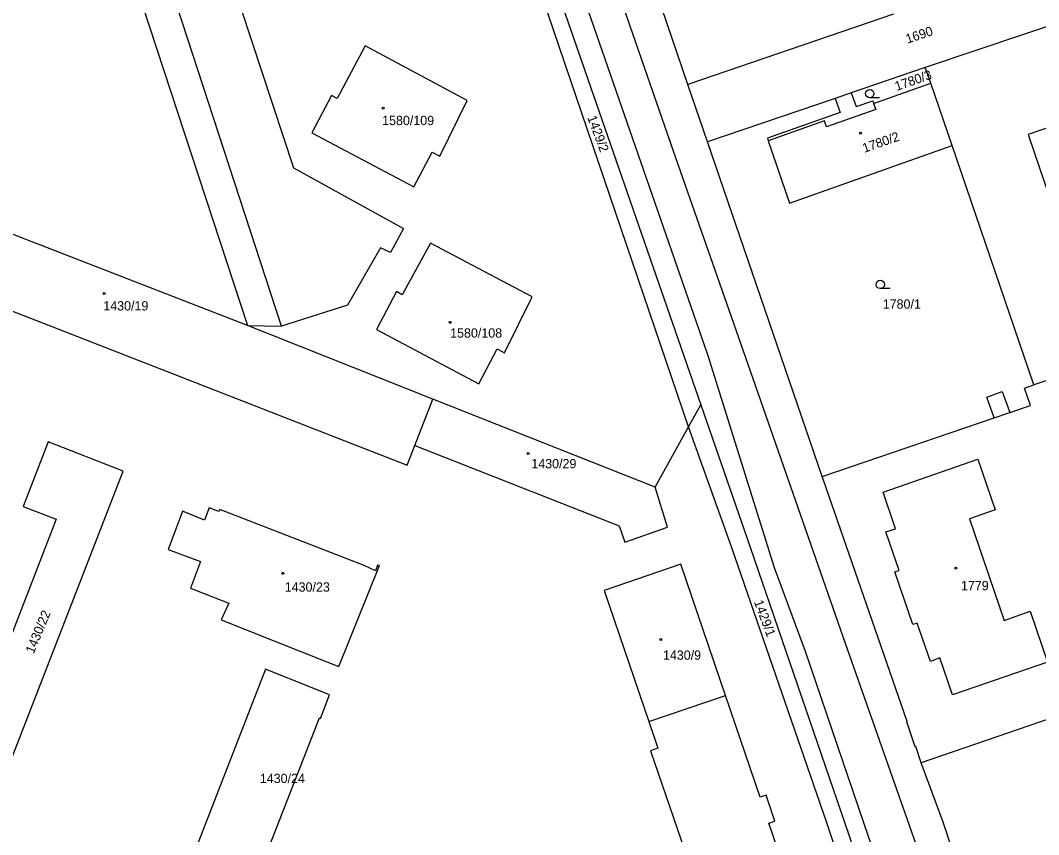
# Model space of a CAD drawing. Extents: x -737240 to -735272, y -1119606 to -1117878.
# Drawn here: x -735865.3 to -735679.6, y -1118834.9 to -1118686.4 of the extents above; entities that cross this region are included whole.
import ezdxf

# ---------------------------------------------------------------- set-up
doc = ezdxf.new("R2010")
doc.units = 0
for name, color, linetype in [('Level 1', 7, 'Continuous'), ('Level 18', 7, 'Continuous'), ('Level 19', 7, 'Continuous'), ('Level 25', 7, 'Continuous'), ('Level 4', 7, 'Continuous')]:
    doc.layers.add(name, color=color, linetype=linetype)

msp = doc.modelspace()

# ---------------------------------------------------------------- linework, layer by layer
at = {"layer": 'Level 1'}
for p, q in [((-735743.45, -1118760.49), (-735777.9, -1118659.21)), ((-735774.81, -1118659.69), (-735741.23, -1118756.51)), ((-735743.62, -1118698.08), (-735748.42, -1118683.99)), ((-735706.07, -1118685.26), (-735743.62, -1118698.08)), ((-735700.35, -1118694.98), (-735713.81, -1118699.59)), ((-735699.29, -1118697.83), (-735700.35, -1118694.98)), ((-735709.72, -1118701.53), (-735699.29, -1118697.83)), ((-735695.39, -1118709.23), (-735699.29, -1118697.83)), ((-735740.02, -1118708.57), (-735743.62, -1118698.08)), ((-735713.81, -1118699.59), (-735716.74, -1118700.61)), ((-735716.74, -1118700.61), (-735740.02, -1118708.57)), ((-735719.09, -1118769.6), (-735740.02, -1118708.57)), ((-735680.49, -1118752.87), (-735695.39, -1118709.23)), ((-735823.87, -1118742.05), (-735817.69, -1118742.18)), ((-735790.07, -1118755.45), (-735823.87, -1118742.05)), ((-735793.39, -1118763.94), (-735790.07, -1118755.45)), ((-735749.58, -1118771.5), (-735790.07, -1118755.45)), ((-735743.45, -1118760.49), (-735741.23, -1118756.51)), ((-735719.09, -1118769.6), (-735687.75, -1118758.87)), ((-735749.58, -1118771.5), (-735743.45, -1118760.49)), ((-735750.72, -1118814.24), (-735736.74, -1118809.5)), ((-735665.87, -1118809.74), (-735701.04, -1118821.77))]:
    msp.add_line(p, q, dxfattribs=at)
for points in [[(-735817.69, -1118742.18), (-735838.65, -1118677.82), (-735864.4, -1118599.8), (-735860.8, -1118595.54), (-735864.62, -1118583.48), (-735866.55, -1118565.64), (-735866.3, -1118553.11), (-735865.89, -1118546.23), (-735864.43, -1118537.4), (-735858.48, -1118504.53), (-735856.26, -1118491.41), (-735855.98, -1118485.53), (-735857.33, -1118477.46), (-735863.02, -1118457.13), (-735869.75, -1118434.93), (-735871.23, -1118430.17)], [(-735839.74, -1118462.4), (-735808.48, -1118550.07), (-735790.87, -1118600.56), (-735770.4, -1118659.74), (-735739.99, -1118747.31), (-735727.84, -1118786.19), (-735722.2, -1118801.44), (-735707.68, -1118844.14), (-735690.7, -1118903.63)], [(-735656.85, -1118959.82), (-735677.7, -1118899.4), (-735694.55, -1118857.78), (-735715.28, -1118798.83), (-735733.91, -1118745.34), (-735746.18, -1118710.4), (-735764.29, -1118658.06), (-735785.07, -1118598.39), (-735802.54, -1118547.91), (-735815.84, -1118509.71), (-735832.49, -1118463.16)], [(-735890.15, -1118471.99), (-735883.87, -1118475.37), (-735897.79, -1118501.36), (-735878.46, -1118511.7), (-735870.93, -1118515.72), (-735873.83, -1118533.49), (-735876.75, -1118551.39), (-735867.45, -1118594.32), (-735865.86, -1118601.75), (-735865.22, -1118603.67), (-735840.68, -1118678.71), (-735844.27, -1118679.88), (-735823.87, -1118742.05)], [(-735819.86, -1118531.46), (-735822.02, -1118528.06), (-735824.64, -1118525.93), (-735829.84, -1118522.94), (-735836.55, -1118521.83), (-735843.27, -1118522.59), (-735848.29, -1118524.5), (-735852.46, -1118527.56), (-735855.95, -1118532.09), (-735858.5, -1118538.73), (-735859.81, -1118546.46), (-735860.26, -1118553.15), (-735860.5, -1118563.98), (-735860.54, -1118573.65), (-735859.56, -1118579.61), (-735815.5, -1118713.26), (-735795.42, -1118724.35), (-735797.8, -1118728.71), (-735799.63, -1118727.86), (-735805.67, -1118738.34), (-735817.69, -1118742.18)], [(-735662.43, -1118684.5), (-735663.76, -1118682.69), (-735700.35, -1118694.98)], [(-735788.82, -1118711.13), (-735783.84, -1118701), (-735802.44, -1118691.06), (-735807.52, -1118700.63), (-735808.58, -1118700.07), (-735812.19, -1118706.88), (-735793.56, -1118716.76), (-735790.19, -1118710.4), (-735788.82, -1118711.13)], [(-735713.81, -1118699.59), (-735712.91, -1118702.12), (-735709.89, -1118701.05), (-735709.72, -1118701.53)], [(-735716.74, -1118700.61), (-735715.83, -1118703.16), (-735729.1, -1118707.86), (-735728.93, -1118708.33)], [(-735663.4, -1118718.6), (-735668.82, -1118702.83), (-735670.85, -1118703.53), (-735670.98, -1118703.15), (-735677.04, -1118705.23), (-735676.91, -1118705.61), (-735681.55, -1118707.22), (-735676.18, -1118722.94)], [(-735728.93, -1118708.33), (-735725.07, -1118719.72), (-735695.39, -1118709.23)], [(-735823.87, -1118742.05), (-735906.13, -1118710.12), (-735911.55, -1118724.03), (-735909.43, -1118724.87), (-735908.69, -1118723.04), (-735794.77, -1118767.48), (-735793.39, -1118763.94)], [(-735795.66, -1118736.44), (-735796.73, -1118735.86), (-735800.35, -1118742.74), (-735781.7, -1118752.69), (-735778.38, -1118746.31), (-735777.05, -1118747.01), (-735771.97, -1118736.83), (-735790.54, -1118727), (-735795.66, -1118736.44)], [(-735658, -1118798.2), (-735669.79, -1118763.59), (-735674.18, -1118750.72), (-735680.49, -1118752.87)], [(-735684.87, -1118757.92), (-735681.11, -1118756.64), (-735682.19, -1118753.45), (-735680.49, -1118752.87)], [(-735687.75, -1118758.87), (-735689.05, -1118755.08), (-735686.29, -1118754.06), (-735684.87, -1118757.92)], [(-735741.23, -1118756.51), (-735732.23, -1118782.47), (-735700.57, -1118874.83), (-735690.7, -1118903.63)], [(-735703.73, -1118876.16), (-735718.34, -1118832.53), (-735735.63, -1118782.39), (-735743.45, -1118760.49)], [(-735872.67, -1118835.65), (-735846.55, -1118768.62), (-735860.21, -1118763.28), (-735864.77, -1118775.03), (-735858.79, -1118777.36), (-735877.4, -1118825.41), (-735883.43, -1118823.05), (-735888.07, -1118834.76), (-735885.31, -1118835.84)], [(-735793.39, -1118763.94), (-735756.15, -1118778.59), (-735755.11, -1118781.53), (-735747.31, -1118778.84), (-735749.58, -1118771.5)], [(-735701.04, -1118821.77), (-735702.03, -1118818.83), (-735702.16, -1118818.88), (-735703.69, -1118814.32), (-735703.62, -1118814.26), (-735718.86, -1118770.26), (-735719.09, -1118769.6)], [(-735802.64, -1118785.8), (-735828.96, -1118775.61), (-735829.09, -1118775.97), (-735830.86, -1118775.27), (-735831.71, -1118777.53), (-735835.73, -1118775.89), (-735838.35, -1118782.9), (-735832.49, -1118785.08), (-735834.29, -1118789.92), (-735827.28, -1118792.69), (-735828.67, -1118795.72), (-735809.44, -1118803.35), (-735807.25, -1118804.21), (-735799.83, -1118785.82), (-735800.17, -1118785.73), (-735800.57, -1118786.76), (-735802.64, -1118785.8)], [(-735736.74, -1118809.5), (-735744.87, -1118785.59), (-735758.88, -1118790.39), (-735750.72, -1118814.24)], [(-735827.17, -1118844.53), (-735823.41, -1118846), (-735810.77, -1118813.62), (-735810.6, -1118813.7), (-735808.96, -1118809.38), (-735820.63, -1118804.69), (-735834.91, -1118841.5), (-735831.1, -1118842.99)], [(-735722.5, -1118851.37), (-735728.81, -1118832.82), (-735727.71, -1118832.45), (-735729.33, -1118827.7), (-735730.42, -1118828.08), (-735736.74, -1118809.5)], [(-735750.72, -1118814.24), (-735749.04, -1118819.15), (-735750.38, -1118819.61), (-735743.42, -1118839.95), (-735742.07, -1118839.49), (-735736.38, -1118856.13)], [(-735686.26, -1118864.85), (-735691.67, -1118849), (-735695.21, -1118838.15), (-735697.06, -1118832.65), (-735701.04, -1118821.77)]]:
    msp.add_lwpolyline(points, dxfattribs=at)
at = {"layer": 'Level 25'}
for p, q in [((-735708.638, -1118700.51), (-735710.42, -1118700.51)), ((-735706.728, -1118735.3), (-735708.51, -1118735.3))]:
    msp.add_line(p, q, dxfattribs=at)
for centre, major_axis, ratio in [((-735710.42, -1118699.754), (0.764, 0), 0.9894236), ((-735799.14, -1118702.39), (0.18, 0), 0.9848078), ((-735712.13, -1118706.94), (0.18, 0), 0.9848078), ((-735708.51, -1118734.544), (0.764, 0), 0.9894236), ((-735850.05, -1118736.22), (0.18, 0), 0.9848078), ((-735786.92, -1118741.46), (0.18, 0), 0.9848078), ((-735772.69, -1118765.38), (0.18, 0), 0.9848078), ((-735817.46, -1118787.24), (0.18, 0), 0.9848078), ((-735694.74, -1118786.3), (0.18, 0), 0.9848078), ((-735748.51, -1118799.28), (0.18, 0), 0.9848078)]:
    msp.add_ellipse(centre, major_axis=major_axis, ratio=ratio, dxfattribs=at)
at = {"layer": 'Level 4'}
msp.add_line((-735687.75, -1118758.87), (-735684.87, -1118757.92), dxfattribs=at)
for points in [[(-735709.72, -1118701.53), (-735709.32, -1118702.66), (-735718.29, -1118705.83), (-735718.69, -1118704.7), (-735728.93, -1118708.33)], [(-735695.32, -1118809.4), (-735697.62, -1118802.67), (-735699.38, -1118803.32), (-735701.79, -1118796.3), (-735702.58, -1118796.57), (-735705.87, -1118786.99), (-735705.06, -1118786.71), (-735707.47, -1118779.66), (-735705.71, -1118779.1), (-735707.99, -1118772.45), (-735690.73, -1118766.4), (-735687.55, -1118775.63), (-735692.26, -1118777.28), (-735685.89, -1118795.82), (-735681.16, -1118794.14), (-735678.01, -1118803.45), (-735695.32, -1118809.4)]]:
    msp.add_lwpolyline(points, dxfattribs=at)

# ---------------------------------------------------------------- texts
at = {"layer": 'Level 18'}
for s, rotation, p in [('1690', 18.39987, (-735703.547, -1118690.633)), ('1780/3', 19.17162, (-735705.521, -1118699.273)), ('1429/2', 290.40435, (-735761.961, -1118704.08)), ('1429/1', 290.67057, (-735731.58, -1118792.456))]:
    msp.add_text(s, height=1.7, rotation=rotation, dxfattribs=at).set_placement(p)
for s, p in [('1780/1', (-735708.06, -1118738.97)), ('1430/24', (-735821.64, -1118825.49))]:
    msp.add_text(s, height=1.7, dxfattribs=at).set_placement(p)
at = {"layer": 'Level 19'}
for s, p in [('1580/109', (-735799.345, -1118705.49)), ('1430/19', (-735850.19, -1118739.3)), ('1580/108', (-735786.945, -1118744.25)), ('1430/29', (-735772.14, -1118768.08)), ('1430/23', (-735817.1, -1118790.58)), ('1779', (-735693.795, -1118790.32)), ('1430/9', (-735748.135, -1118803))]:
    msp.add_text(s, height=1.7, dxfattribs=at).set_placement(p)
for s, rotation, p in [('1780/2', 19.28304, (-735711.422, -1118710.558)), ('1430/22', 67.49442, (-735862.88, -1118802.01))]:
    msp.add_text(s, height=1.7, rotation=rotation, dxfattribs=at).set_placement(p)

doc.saveas('drawing.dxf')
